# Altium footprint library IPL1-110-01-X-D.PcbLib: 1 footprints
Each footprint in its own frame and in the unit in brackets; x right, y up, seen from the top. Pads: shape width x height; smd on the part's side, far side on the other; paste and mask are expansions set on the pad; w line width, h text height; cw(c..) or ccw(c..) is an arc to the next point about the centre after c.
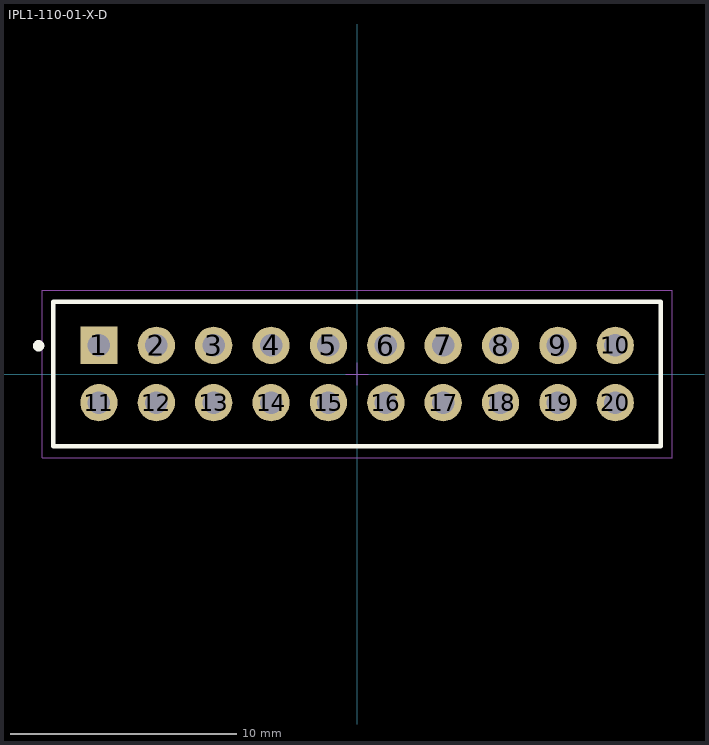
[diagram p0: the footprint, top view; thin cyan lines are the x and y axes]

## IPL1-110-01-X-D [mm] "2.54mm pitch, isolated power locking header"
height 8.13
pads (20):
  rect 1.65x1.65 / inner round 1.65 / far side rect 1.65x1.65 hole 1 mask+0: 1(-11.43,1.27)
  round 1.65 hole 1 mask+0: 2(-8.89,1.27) 3(-6.35,1.27) 4(-3.81,1.27) 5(-1.27,1.27) 6(1.27,1.27) 7(3.81,1.27) 8(6.35,1.27) 9(8.89,1.27) 10(11.43,1.27) 11(-11.43,-1.27) 12(-8.89,-1.27) 13(-6.35,-1.27) 14(-3.81,-1.27) 15(-1.27,-1.27) 16(1.27,-1.27) 17(3.81,-1.27) 18(6.35,-1.27) 19(8.89,-1.27) 20(11.43,-1.27)
Top Overlay:
  circle w0.25: c-14.1,1.25 r0.125
  lines w0.2: -13.45,-3.2 13.45,-3.2 13.45,3.2 -13.45,3.2 -13.45,-3.2
Mechanical 12:
  lines w0.001: -13.45,-3.2 13.45,-3.2 13.45,3.2 -13.45,3.2 -13.45,-3.2
Mechanical 13:
  lines w0.1: -13.45,-3.2 13.45,-3.2 13.45,3.2 -13.45,3.2 -13.45,-3.2
  text ".Designator" at 0,0 h1.52
Mechanical 15:
  lines w0.05: -0.5,0 0.5,0 ; 0,-0.5 0,0.5 ; -13.95,-3.7 13.95,-3.7 13.95,3.7 -13.95,3.7 -13.95,-3.7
